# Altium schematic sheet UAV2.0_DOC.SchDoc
size A4
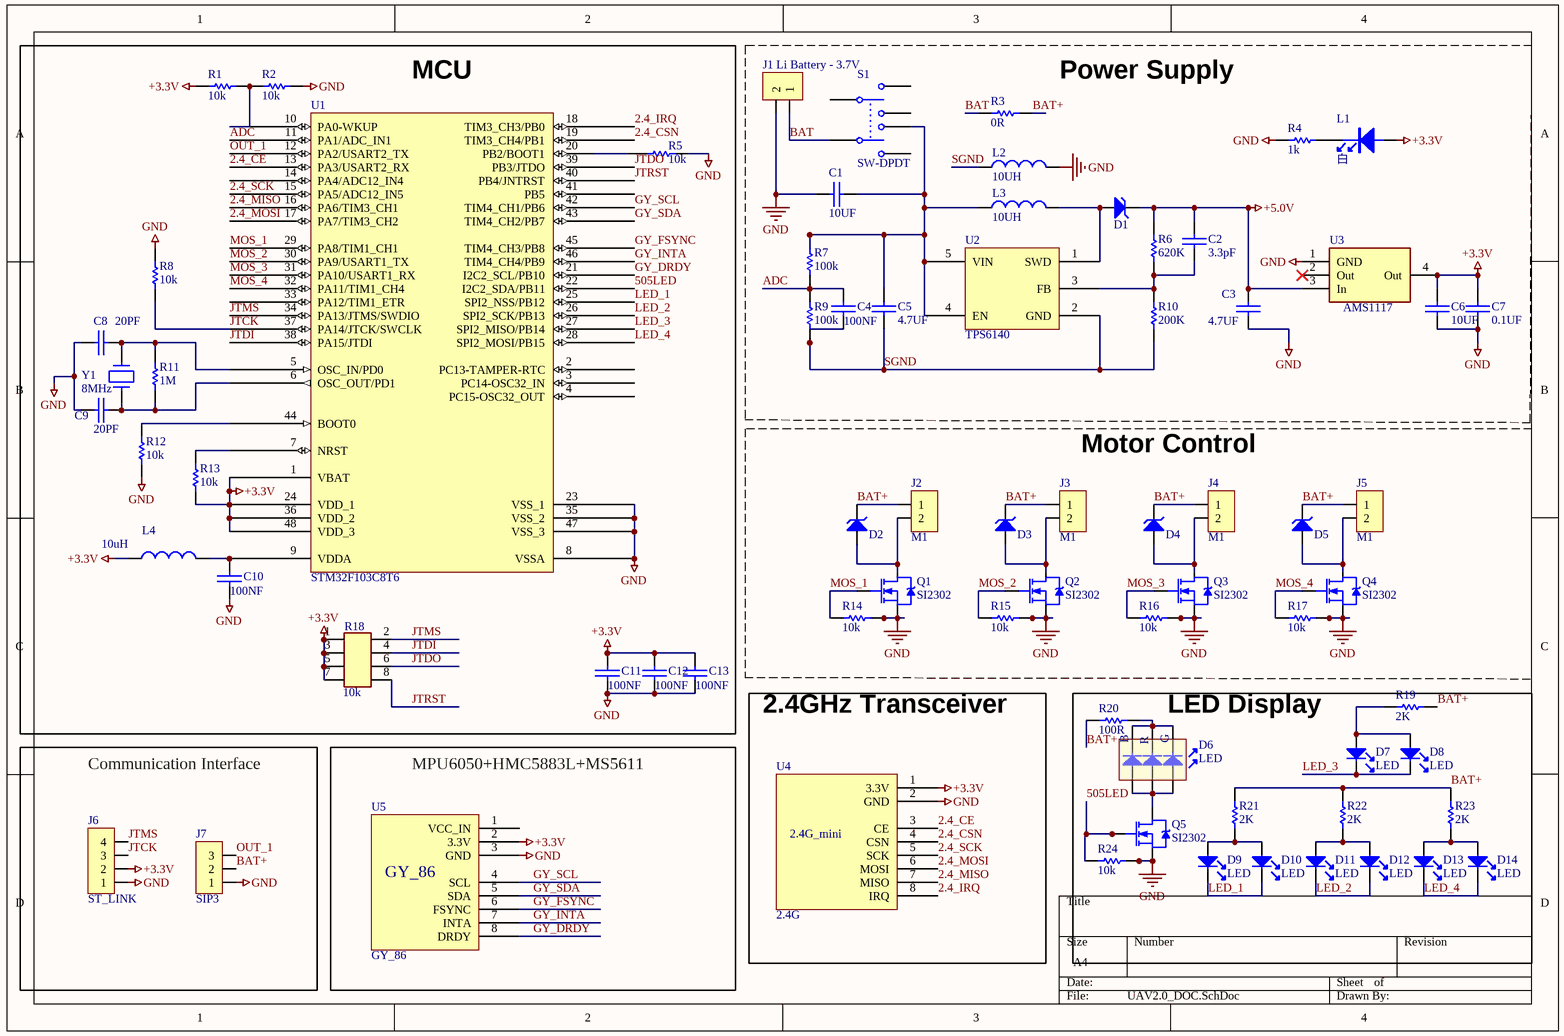
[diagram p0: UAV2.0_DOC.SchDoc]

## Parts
C1  10UF  [1206C]
C2  3.3pF  [0805C]
C3  4.7UF  [1206C]
C4  100NF  [0805C]
C5  4.7UF  [0805C]
C6  10UF  [1206C]
C7  0.1UF  [0805C]
C8  20PF  [0805C]
C9  20PF  [0805C]
C10  100NF  [0805C]
C11  100NF  [0805C]
C12  100NF  [0805C]
C13  100NF  [0805C]
D1  DIODE-S  [C_SMA_3216]  (value not drawn)
D2  DIODE-S  [C_SMA_3216]  (value not drawn)
D3  DIODE-S  [C_SMA_3216]  (value not drawn)
D4  DIODE-S  [C_SMA_3216]  (value not drawn)
D5  DIODE-S  [C_SMA_3216]  (value not drawn)
D6  LED  [LED5050_RGB]
D7  LED  [0805D]
D8  LED  [0805D]
D9  LED  [0805D]
D10  LED  [0805D]
D11  LED  [0805D]
D12  LED  [0805D]
D13  LED  [0805D]
D14  LED  [0805D]
J1  Li Battery - 3.7V  [P2_2.0-2]
J2  M1  [P2_2.0-1]
J3  M1  [P2_2.0-1]
J4  M1  [P2_2.0-1]
J5  M1  [P2_2.0-1]
J6  ST_LINK  [P4_2.54-1]
J7  SIP3  [PC_3]
L1  白  [D0805]
L2  10UH  [1206]
L3  10UH  [1206]
L4  Val: 10uH  [R0805]  (hidden comment: INDUCTOR)
Q1  SI2302  [SI2302]
Q2  SI2302  [SI2302]
Q3  SI2302  [SI2302]
Q4  SI2302  [SI2302]
Q5  SI2302  [SI2302]
R1  Val: 10k  [R0805]  (hidden comment: RES)
R2  Val: 10k  [R0805]  (hidden comment: RES)
R3  0R  [2512R - duplicate]
R4  value 1k  [R0805]  (hidden comment: Res1)
R5  Val: 10k  [R0805]  (hidden comment: RES)
R6  620K  [0805R]
R7  Val: 100k  [R0805]  (hidden comment: RES)
R8  Val: 10k  [R0805]  (hidden comment: RES)
R9  Val: 100k  [R0805]  (hidden comment: RES)
R10  200K  [0805R]
R11  Val: 1M  [R0805]  (hidden comment: RES)
R12  Val: 10k  [R0805]  (hidden comment: RES)
R13  Val: 10k  [R0805]  (hidden comment: RES)
R14  Val: 10k  [R0805]  (hidden comment: RES)
R15  Val: 10k  [R0805]  (hidden comment: RES)
R16  Val: 10k  [R0805]  (hidden comment: RES)
R17  Val: 10k  [R0805]  (hidden comment: RES)
R18  10k  [8P4R_0603]
R19  Val: 2K  [R0805]  (hidden comment: RES)
R20  100R  [0805R]
R21  Val: 2K  [R0805]  (hidden comment: RES)
R22  Val: 2K  [R0805]  (hidden comment: RES)
R23  Val: 2K  [R0805]  (hidden comment: RES)
R24  Val: 10k  [R0805]  (hidden comment: RES)
S1  SW-DPDT  [KEY_KFT7.0]
U1  STM32F103C8T6  [LQFP48_N]
U2  TPS6140  [SOT-23-5]
U3  AMS1117  [ZZ311]
U4  2.4G  [2.4G_mini]
U5  GY_86  [P8_2.54-1]
Y1  Val: 8MHz  [Y2]  (hidden comment: CRYSTAL1)

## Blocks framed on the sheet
MCU: C8-C13 L4 R1 R2 R5 R8 R11-R13 R18 U1 Y1
Motor Control: D2-D5 J2-J5 Q1-Q4 R14-R17
2.4GHz Transceiver: U4
LED Display: D6-D14 Q5 R19-R24
Communication Interface: J6 J7
MPU6050+HMC5883L+MS5611: U5

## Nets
+3.3V: C6.1 C7.1 C11.1 C12.1 C13.1 J6.2 L1.1 L4.1 R1.2 R13.1 R18.1(P) R18.3(P) R18.5(P) R18.7(P) U1.1(VBAT) U1.24(VDD_1) U1.36(VDD_2) U1.48(VDD_3) U3.4(Out) U4.1(3.3V) U5.2(3.3V)
+5.0V: C2.1 C3.1 D1.2 R6.2 U3.3(In)
GND: C1.1 C3.2 C6.2 C7.2 C8.1 C9.1 C10.2 C11.2 C12.2 C13.2 J1.2 J6.1 J7.1 L2.1 Q1.2(S) Q2.2(S) Q3.2(S) Q4.2(S) Q5.2(S) R2.1 R4.2 R5.2 R8.2 R12.1 R14.1 R15.1 R16.1 R17.1 R24.1 U1.8(VSSA) U1.23(VSS_1) U1.35(VSS_2) U1.47(VSS_3) U3.1(GND) U4.2(GND) U5.3(GND)
2.4_CE: U1.13(PA3/USART2_RX) U4.3(CE)
2.4_CSN: U1.19(TIM3_CH4/PB1) U4.4(CSN)
2.4_IRQ: U1.18(TIM3_CH3/PB0) U4.8(IRQ)
2.4_MISO: U1.16(PA6/TIM3_CH1) U4.7(MISO)
2.4_MOSI: U1.17(PA7/TIM3_CH2) U4.6(MOSI)
2.4_SCK: U1.15(PA5/ADC12_IN5) U4.5(SCK)
505LED: Q5.1(G) R24.2 U1.22(I2C2_SDA/PB11)
ADC: C4.1 R7.2 R9.1 U1.11(PA1/ADC_IN1)
BAT: J1.1 R3.1 S1.4
BAT+: D2.2 D3.2 D4.2 D5.2 J2.1 J3.1 J4.1 J5.1 J7.2 R3.2 R19.2 R20.1 R21.1 R22.1 R23.1
GY_DRDY: U1.21(I2C2_SCL/PB10) U5.8(DRDY)
GY_FSYNC: U1.45(TIM4_CH3/PB8) U5.6(FSYNC)
GY_INTA: U1.46(TIM4_CH4/PB9) U5.7(INTA)
GY_SCL: U1.42(TIM4_CH1/PB6) U5.4(SCL)
GY_SDA: U1.43(TIM4_CH2/PB7) U5.5(SDA)
JTCK: J6.3 R8.1 U1.37(PA14/JTCK/SWCLK)
JTDI: R18.4(P) U1.38(PA15/JTDI)
JTDO: R18.6(P) U1.39(PB3/JTDO)
JTMS: J6.4 R18.2(P) U1.34(PA13/JTMS/SWDIO)
JTRST: R18.8(P) U1.40(PB4/JNTRST)
LED_1: D9.2 D10.2 U1.25(SPI2_NSS/PB12)
LED_2: D11.2 D12.2 U1.26(SPI2_SCK/PB13)
LED_3: D7.2 D8.2 U1.27(SPI2_MISO/PB14)
LED_4: D13.2 D14.2 U1.28(SPI2_MOSI/PB15)
MOS_1: Q1.1(G) R14.2 U1.29(PA8/TIM1_CH1)
MOS_2: Q2.1(G) R15.2 U1.30(PA9/USART1_TX)
MOS_3: Q3.1(G) R16.2 U1.31(PA10/USART1_RX)
MOS_4: Q4.1(G) R17.2 U1.32(PA11/TIM1_CH4)
OUT_1: J7.3 U1.12(PA2/USART2_TX)
SGND: C4.2 C5.2 L2.2 R9.2 R10.1 U2.2(GND)
NetC1_2: C1.2 C5.1 L3.2 R7.1 S1.5 U2.4(EN) U2.5(VIN)
NetC2_2: C2.2 R6.1 R10.2 U2.3(FB)
NetC8_2: C8.2 R11.2 U1.5(OSC_IN/PD0) Y1.2
NetC9_2: C9.2 R11.1 U1.6(OSC_OUT/PD1) Y1.1
NetC10_1: C10.1 L4.2 U1.9(VDDA)
NetD1_1: D1.1 L3.1 U2.1(SWD)
NetD2_1: D2.1 J2.2 Q1.3(D)
NetD3_1: D3.1 J3.2 Q2.3(D)
NetD4_1: D4.1 J4.2 Q3.3(D)
NetD5_1: D5.1 J5.2 Q4.3(D)
NetD6_1: D6.1 D6.2 D6.3 R20.2
NetD6_4: D6.4 D6.5 D6.6 Q5.3(D)
NetD7_1: D7.1 D8.1 R19.1
NetD9_1: D9.1 D10.1 R21.2
NetD11_1: D11.1 D12.1 R22.2
NetD13_1: D13.1 D14.1 R23.2
NetL1_2: L1.2 R4.1
NetR1_1: R1.1 R2.2 U1.10(PA0-WKUP)
NetR5_1: R5.1 U1.20(PB2/BOOT1)
NetR12_2: R12.2 U1.44(BOOT0)
NetR13_2: R13.2 U1.7(NRST)

Not connected (* = marked no-connect by the designer): S1 1 2 3 6; U1 2(PC13-TAMPER-RTC) 3(PC14-OSC32_IN) 4(PC15-OSC32_OUT) 14(PA4/ADC12_IN4) 33(PA12/TIM1_ETR) 41(PB5); U3 2(Out)*; U5 1(VCC_IN)

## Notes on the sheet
- (near R3) Power Supply

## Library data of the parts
C1-C13 = CAP: Capacitor/小容量电容
D1-D5 = DIODE-S: SCHOTTKEY
D6 = LED_5050RGB
J1-J5 = SIP2
J6 = SIP4
L1 = LED
L2 L3 = L
R1 R2 R5 R7-R9 R11-R17 R19 R21-R24 = RES: Semiconductor Resistor
R3 = Res_1
R4 = Res1: Resistor
R6 R10 R20 = Res
R18 = 8P4R_0603
S1 = SW-DPDT: Double-Pole, Double-Throw Switch
U1 = STM32F103C8T6: STM32 ARM-based 32-bit MCU with 64 Kbytes Flash, 48-pin LQFP, Industrial Temperature
U3 = AMS1117: Header, 2-Pin
U4 = 2.4G_mini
